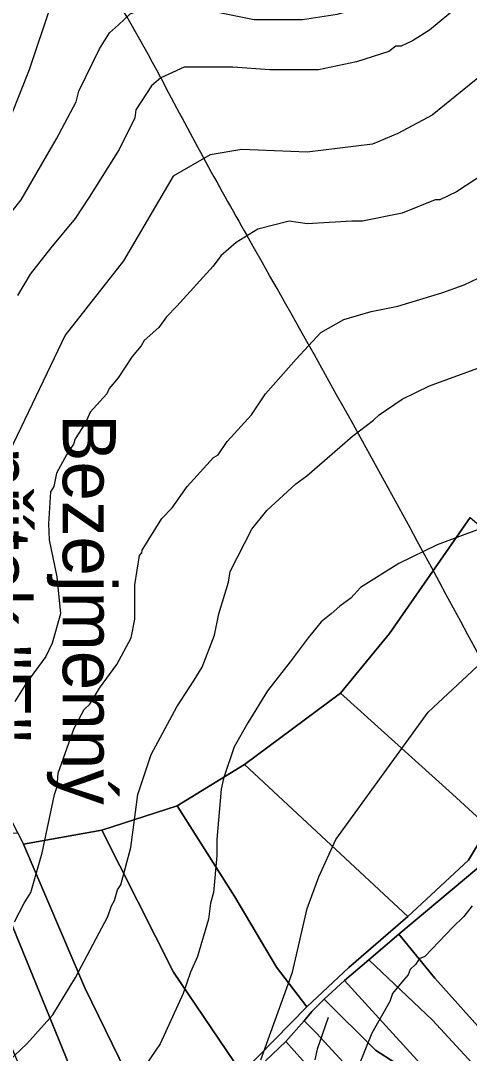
# Model space of a CAD drawing. Extents: x -510989 to -501240, y -1184665 to -1176089.
# Drawn here: x -504294.9 to -504125.8, y -1182831.5 to -1182442.4 of the extents above; entities that cross this region are included whole.
import ezdxf

# ---------------------------------------------------------------- set-up
doc = ezdxf.new("R2010")
doc.units = 0
for name, color, linetype in [('lesni_pozemek', 7, 'Continuous'), ('NAVRH_rozvodnice', 7, 'Continuous'), ('STAV_zaplavove_uzemi', 7, 'Continuous'), ('trvaly_travni_porost', 7, 'Continuous'), ('vrstevnice_01', 7, 'Continuous'), ('vrstevnice_02', 7, 'Continuous'), ('vrstevnice_03', 7, 'Continuous')]:
    doc.layers.add(name, color=color, linetype=linetype)

msp = doc.modelspace()

# ---------------------------------------------------------------- linework, layer by layer
at = {"layer": 'lesni_pozemek'}
for points in [[(-504125.54, -1182629.68), (-504155.94, -1182673.32), (-504174.32, -1182695.83), (-504210.52, -1182722.69), (-504235.93, -1182738.25), (-504264.25, -1182747.48), (-504293.81, -1182752.72), (-504295.93, -1182748.47), (-504310.85, -1182719.26), (-504318.59, -1182708.58), (-504328.95, -1182695.62), (-504341.55, -1182683.01), (-504348.64, -1182647.73), (-504338.72, -1182629.02), (-504335.18, -1182603.23), (-504338, -1182582.37), (-504351.89, -1182548.22), (-504366.04, -1182490.92), (-504369.86, -1182481.57), (-504383.74, -1182456.35), (-504376.66, -1182443.95), (-504372.24, -1182440.22)], [(-504089.79, -1182857.01), (-504113.93, -1182830.98), (-504138.84, -1182803.26), (-504152.42, -1182786.67), (-504123.07, -1182761.98), (-504057.27, -1182842.9)]]:
    msp.add_lwpolyline(points, dxfattribs=at)
msp.add_lwpolyline([(-504108.08, -1182644.43), (-504093.8, -1182657.06), (-504103.38, -1182693.45), (-504117.63, -1182740.83), (-504118.68, -1182746.36), (-504132.13, -1182733.89), (-504174.32, -1182695.83), (-504155.94, -1182673.32), (-504125.54, -1182629.68)], close=True, dxfattribs=at)
at = {"layer": 'NAVRH_rozvodnice'}
for centre, radius, start, end in [((-504699.48, -1182702.89), 516.01, 27.5774, 33.444), ((-502627.68, -1181620.81), 1821.35, 207.57737, 209.71025), ((-509825.79, -1185728.25), 6466.23, 28.085774, 29.710253)]:
    msp.add_arc(centre, radius, start, end, dxfattribs=at)
at = {"layer": 'STAV_zaplavove_uzemi'}
msp.add_spline([(-502250.32, -1184002.61), (-502355.07, -1183875.41), (-502442.37, -1183790.61), (-502477.29, -1183700.82), (-502532.16, -1183578.61), (-502567.08, -1183448.91), (-502626.05, -1183402.34), (-502705.41, -1183380.59), (-502814.2, -1183349.87), (-502882.03, -1183297.39), (-502931.95, -1183237.24), (-503042.02, -1183107.97), (-503139.64, -1183018.94), (-503222.14, -1182957.59), (-503308.56, -1182839.96), (-503316.24, -1182784.92), (-503330.32, -1182756.77), (-503348.24, -1182719.65), (-503334.16, -1182651.82), (-503323.92, -1182595.5), (-503313.68, -1182526.39), (-503294.1, -1182480.5), (-503251.86, -1182396.03), (-503229.34, -1182314.37), (-503216.1, -1182227.15), (-503242.43, -1182174.5), (-503271.86, -1182129.59), (-503287.34, -1182081.58), (-503343.88, -1182028.1), (-503361.79, -1182008.91), (-503396.35, -1181952.59), (-503442.43, -1181933.39), (-503497.46, -1181888.6), (-503525.62, -1181860.44), (-503528.18, -1181837.4), (-503548.66, -1181767.01), (-503558.9, -1181729.89), (-503576.82, -1181682.53), (-503578.1, -1181621.1), (-503567.86, -1181572.46), (-503552.5, -1181536.63), (-503538.04, -1181458.36), (-503518.33, -1181411.9), (-503509.88, -1181341.51), (-503497.21, -1181207.63), (-503499.77, -1181097.56), (-503498.02, -1181031.35), (-503510.82, -1180970.85), (-503549.22, -1180952.23), (-503571.32, -1180940.6), (-503605.07, -1180937.11), (-503651.61, -1180939.44), (-503671.39, -1180917.33), (-503679.53, -1180892.89), (-503713.27, -1180871.95), (-503727.24, -1180859.15), (-503734.22, -1180833.55), (-503728.4, -1180799.81), (-503741.2, -1180770.72), (-503722.82, -1180725.17), (-503721.54, -1180703.41), (-503731.78, -1180697.01), (-503767.61, -1180699.57), (-503790.65, -1180697.01), (-503817.53, -1180697.01), (-503861.04, -1180686.77), (-503889.2, -1180675.25), (-503900.72, -1180668.85), (-503953.2, -1180679.09), (-503997.99, -1180697.01), (-504063.27, -1180722.61), (-504109.34, -1180749.49), (-504142.62, -1180776.36), (-504177.18, -1180796.84), (-504211.73, -1180817.32), (-504414.98, -1180961.5), (-504472.7, -1180998.11), (-504544.51, -1181068.5), (-504600.82, -1181143.12), (-504621.94, -1181196.62), (-504641.65, -1181267.01), (-504660.25, -1181350.62), (-504634.7, -1181398.32), (-504617.66, -1181447.72), (-504600.62, -1181492.01), (-504587, -1181548.23), (-504592.11, -1181628.29), (-504569.96, -1181682.81), (-504568.26, -1181664.07), (-504554.63, -1181621.48), (-504547.82, -1181597.63)], degree=3, dxfattribs=at)
at = {"layer": 'trvaly_travni_porost'}
for points in [[(-504174.32, -1182695.83), (-504132.13, -1182733.89), (-504118.68, -1182746.36), (-504120.13, -1182748.75), (-504126.2, -1182758.75), (-504149.03, -1182779.94), (-504210.52, -1182722.69)], [(-504210.52, -1182722.69), (-504149.03, -1182779.94), (-504171.3, -1182799.16), (-504187.04, -1182813.97), (-504198.46, -1182799.13), (-504214.21, -1182772.59), (-504235.93, -1182738.25)], [(-504235.93, -1182738.25), (-504214.21, -1182772.59), (-504198.46, -1182799.13), (-504187.04, -1182813.97), (-504211.58, -1182839.08), (-504237.33, -1182800.97), (-504264.25, -1182747.48)], [(-504295.93, -1182748.47), (-504293.81, -1182752.72), (-504270.73, -1182806.86), (-504242.32, -1182864.99), (-504257.2, -1182871.75), (-504275.32, -1182839), (-504299.12, -1182780.84), (-504310.8, -1182749.04)], [(-504264.25, -1182747.48), (-504237.33, -1182800.97), (-504211.58, -1182839.08), (-504225.53, -1182851.98), (-504242.32, -1182864.99), (-504270.73, -1182806.86), (-504293.81, -1182752.72)], [(-504299.12, -1182780.84), (-504275.32, -1182839), (-504257.2, -1182871.75), (-504274.24, -1182874.7), (-504286.34, -1182851.87), (-504290.77, -1182847.15), (-504308.05, -1182806.06), (-504315.84, -1182788.78)], [(-504163.77, -1182796.35), (-504152.42, -1182786.67), (-504138.84, -1182803.26), (-504113.93, -1182830.98), (-504089.79, -1182857.01), (-504068.07, -1182882.7), (-504047.02, -1182910.28), (-504031.75, -1182929.1), (-504022.97, -1182939.87), (-504000.89, -1182967.41), (-504006.62, -1182971.66), (-504010.43, -1182974.49), (-504017.32, -1182966.46), (-504023.18, -1182959.19), (-504028.9, -1182951.41), (-504049.39, -1182924.3), (-504062.53, -1182907.58), (-504078.64, -1182886.84), (-504089.37, -1182876.38), (-504101.08, -1182860.99), (-504139.67, -1182819.08)], [(-504172.88, -1182804.13), (-504163.77, -1182796.35), (-504139.67, -1182819.08), (-504101.08, -1182860.99), (-504089.37, -1182876.38), (-504078.64, -1182886.84), (-504062.53, -1182907.58), (-504049.39, -1182924.3), (-504028.9, -1182951.41), (-504023.18, -1182959.19), (-504017.32, -1182966.46), (-504010.43, -1182974.49), (-504019.83, -1182981.13), (-504044.66, -1182948.73), (-504072, -1182912.53), (-504083.62, -1182897.98), (-504109.55, -1182869.88), (-504142.94, -1182836.87)], [(-504180.5, -1182811.16), (-504172.88, -1182804.13), (-504142.94, -1182836.87), (-504109.55, -1182869.88), (-504083.62, -1182897.98), (-504072, -1182912.53), (-504044.66, -1182948.73), (-504019.83, -1182981.13), (-504029.18, -1182987.53), (-504067.9, -1182936.88), (-504092.79, -1182905.32), (-504107.58, -1182890.35), (-504119.57, -1182873.82), (-504153.82, -1182835.14), (-504161.16, -1182830.35)], [(-504185.12, -1182815.82), (-504180.5, -1182811.16), (-504161.16, -1182830.35), (-504153.82, -1182835.14), (-504119.57, -1182873.82), (-504107.58, -1182890.35), (-504092.79, -1182905.32), (-504067.9, -1182936.88), (-504029.18, -1182987.53), (-504037.4, -1182993.19), (-504059.47, -1182965.15), (-504087.66, -1182929.02), (-504109.07, -1182903.19), (-504142.66, -1182868.27), (-504183.42, -1182823.91), (-504188.1, -1182819.35)]]:
    msp.add_lwpolyline(points, close=True, dxfattribs=at)
for points in [[(-504211.58, -1182839.08), (-504187.04, -1182813.97), (-504171.3, -1182799.16), (-504149.03, -1182779.94), (-504126.2, -1182758.75), (-504120.13, -1182748.75), (-504118.8, -1182751), (-504120.45, -1182755.66), (-504123.07, -1182761.98), (-504152.42, -1182786.67), (-504163.77, -1182796.35), (-504172.88, -1182804.13), (-504180.5, -1182811.16), (-504185.12, -1182815.82), (-504188.1, -1182819.35), (-504194.92, -1182827.03), (-504202.6, -1182834.38)], [(-504182.48, -1182841.19), (-504194.92, -1182827.03), (-504188.1, -1182819.35), (-504183.42, -1182823.91), (-504142.66, -1182868.27)], [(-504202.6, -1182834.38), (-504194.92, -1182827.03), (-504182.48, -1182841.19)]]:
    msp.add_lwpolyline(points, dxfattribs=at)
at = {"layer": 'vrstevnice_01'}
for points in [[(-504283.59, -1182437), (-504291.69, -1182461), (-504298.5, -1182478)], [(-504129.91, -1182437), (-504140.81, -1182446), (-504147.31, -1182450), (-504151.5, -1182452), (-504153.59, -1182452), (-504156.19, -1182454), (-504168.31, -1182458), (-504182.69, -1182461), (-504190.81, -1182461), (-504201, -1182461), (-504215, -1182460), (-504223.5, -1182460), (-504233.31, -1182460), (-504242.09, -1182464), (-504245.59, -1182467), (-504251.5, -1182476), (-504251.91, -1182479), (-504257.81, -1182491), (-504269, -1182509), (-504274.31, -1182517), (-504283.5, -1182528), (-504291.31, -1182538), (-504296, -1182546)], [(-504120.19, -1182500), (-504130.69, -1182507), (-504136.91, -1182510), (-504138.69, -1182510), (-504151.19, -1182515), (-504166.09, -1182518), (-504170.09, -1182518), (-504187, -1182519), (-504193.69, -1182518), (-504205.5, -1182521), (-504213.69, -1182526), (-504219.41, -1182531), (-504222.31, -1182535), (-504236.09, -1182550), (-504239.91, -1182554), (-504242.81, -1182558), (-504248.31, -1182563), (-504249.5, -1182565), (-504252.91, -1182569), (-504258.09, -1182577), (-504261.5, -1182581), (-504262.41, -1182583), (-504268.69, -1182590), (-504270.5, -1182594), (-504274.31, -1182600), (-504275, -1182602), (-504277.59, -1182606), (-504281.31, -1182613), (-504282.41, -1182618), (-504283.59, -1182620), (-504284.41, -1182632), (-504284.19, -1182638), (-504281.19, -1182652), (-504279.81, -1182666), (-504283, -1182677), (-504285.41, -1182682), (-504292.69, -1182692), (-504297.09, -1182699)], [(-504308.59, -1182843), (-504292.59, -1182828), (-504282.69, -1182817), (-504274.19, -1182803), (-504262, -1182780), (-504260.69, -1182776), (-504259.5, -1182774), (-504258.41, -1182770), (-504257.19, -1182768), (-504253.31, -1182754), (-504250.69, -1182734), (-504245.69, -1182719), (-504236, -1182701), (-504229.5, -1182691), (-504226.5, -1182686), (-504221.91, -1182674), (-504220.19, -1182666), (-504216.59, -1182654), (-504216, -1182650), (-504207.81, -1182634), (-504202.19, -1182627), (-504191.19, -1182617), (-504187.09, -1182614), (-504169.81, -1182599), (-504161.91, -1182593), (-504159.81, -1182591), (-504151.09, -1182585), (-504140.81, -1182580), (-504083.41, -1182559)], [(-504204.41, -1182834), (-504192.41, -1182801), (-504186.91, -1182777), (-504182.59, -1182765), (-504176.19, -1182751), (-504141.31, -1182703), (-504121, -1182684), (-504110.5, -1182678), (-504097.81, -1182675), (-504080.91, -1182674), (-504062.69, -1182678), (-504050.5, -1182683), (-504040.5, -1182690), (-504017.5, -1182710), (-504003.09, -1182729), (-503992.41, -1182745), (-503979.41, -1182774), (-503975.41, -1182787), (-503974.09, -1182803), (-503975.41, -1182848)]]:
    msp.add_lwpolyline(points, dxfattribs=at)
at = {"layer": 'vrstevnice_02'}
for points in [[(-504265.19, -1182453), (-504261.41, -1182447), (-504258, -1182444), (-504253.69, -1182440), (-504249.41, -1182438), (-504247.31, -1182437), (-504234.31, -1182436), (-504221.91, -1182439), (-504206.91, -1182442), (-504198.81, -1182442), (-504188.69, -1182442), (-504175.69, -1182440), (-504164.09, -1182437), (-504151.41, -1182431), (-504143.31, -1182424), (-504139.5, -1182419), (-504124.81, -1182395)], [(-504301.81, -1182519), (-504294.69, -1182510), (-504281.31, -1182487), (-504274, -1182473), (-504272.91, -1182469), (-504265.19, -1182453)], [(-504121.31, -1182463), (-504139.91, -1182478), (-504152.81, -1182485), (-504162.31, -1182489), (-504187, -1182492), (-504211.5, -1182491), (-504223.5, -1182493), (-504237.41, -1182501), (-504256.09, -1182533), (-504278.09, -1182561), (-504306, -1182619), (-504310.59, -1182630), (-504313.69, -1182648), (-504311.91, -1182665), (-504313.5, -1182684), (-504333.19, -1182741), (-504335.69, -1182764)], [(-504297.19, -1182782), (-504293.5, -1182775), (-504291.09, -1182771), (-504286.81, -1182756), (-504282.09, -1182734), (-504281.09, -1182731), (-504280.69, -1182726), (-504274.69, -1182709), (-504271, -1182702), (-504268.81, -1182700), (-504265.19, -1182694), (-504258.69, -1182685), (-504253.19, -1182675), (-504251.91, -1182668), (-504251.91, -1182655), (-504250.09, -1182644), (-504249.19, -1182643), (-504249.09, -1182642), (-504241.69, -1182630), (-504237.81, -1182626), (-504232.09, -1182618), (-504222.19, -1182607), (-504220.41, -1182606), (-504217.09, -1182601), (-504207.91, -1182591), (-504202.59, -1182583), (-504191.09, -1182570), (-504181.81, -1182560), (-504173.09, -1182555), (-504162.81, -1182552), (-504152.81, -1182550), (-504136.19, -1182545), (-504127.81, -1182542), (-504117.31, -1182537)], [(-504122.09, -1182634), (-504137.91, -1182640), (-504152.41, -1182647), (-504166.91, -1182656), (-504170.5, -1182660), (-504174.59, -1182663), (-504177.91, -1182666), (-504181.69, -1182669), (-504186.5, -1182675), (-504188.81, -1182678), (-504193.31, -1182684), (-504201.91, -1182695), (-504209.31, -1182707), (-504214.41, -1182716), (-504218.5, -1182728), (-504219.31, -1182732), (-504221, -1182751), (-504221, -1182757), (-504222.19, -1182771), (-504223.31, -1182775), (-504224.09, -1182781), (-504228.31, -1182795), (-504230.91, -1182801), (-504233.59, -1182809), (-504242.31, -1182828), (-504256.59, -1182849)], [(-504124.81, -1182776), (-504127.91, -1182780), (-504132.09, -1182784), (-504142.59, -1182795), (-504144.81, -1182796), (-504146, -1182798), (-504148.19, -1182800), (-504148.91, -1182802), (-504150.59, -1182804)], [(-504150.59, -1182804), (-504154.81, -1182809), (-504155.81, -1182812), (-504162.59, -1182824), (-504167.91, -1182837)]]:
    msp.add_lwpolyline(points, dxfattribs=at)
at = {"layer": 'vrstevnice_03'}
msp.add_lwpolyline([(-504179.09, -1182818), (-504183.19, -1182830), (-504184, -1182834)], dxfattribs=at)

# ---------------------------------------------------------------- texts
at = {"layer": 'NAVRH_rozvodnice'}
for s, p in [('Bezejmenný', (-504278.99, -1182590.69)), ('přítok "E"', (-504310.99, -1182603.25))]:
    msp.add_text(s, height=20, rotation=270, dxfattribs=at).set_placement(p)

doc.saveas('drawing.dxf')
